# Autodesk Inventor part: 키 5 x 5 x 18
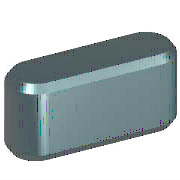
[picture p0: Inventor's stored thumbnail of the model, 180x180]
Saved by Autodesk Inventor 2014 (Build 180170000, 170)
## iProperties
Created: 2012-02
Part Number: 키 5 x 5 x 18
Material: 강철, 연강
Description: 키 및 해당 키홈
Document SubType Name: Modeling
Standard: KS B 1311
Designer: P15F
Standards Organization: KS
Language: ko-KR
Size Designation: 5 x 5 x 18
Categories: <MemberInstance><Categories><Category DisplayName="샤프트 부품" InternalName="7f7aeb1f-a693-4053-b835-cee3144e0d98" Mnemonic="SHFT"><Category DisplayName="키" Interna
Density: 1 g/cm^3
Appearance: Yellow
IsCustomPart: 1
Author: P15F
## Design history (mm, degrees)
sketch "스케치1"
  geometry: L1 (2.5, 2.5)-(15.5, 2.5); L2 (15.5, -2.5)-(2.5, -2.5); L3 (0, 9.4)-(0, -7.4) reference; L4 (-5, 0)-(30, 0) reference; L5 (18, 0)-(18, 7); A1 r 2.5 centre (2.5, 0) between (2.5, 2.5) and (2.5, -2.5); A2 r 2.5 centre (15.5, 0) between (15.5, -2.5) and (15.5, 2.5)
  constraints: 6 end point, 5 point on circle, 4 tangent, 3 point on line, 2 centre point, 1 horizontal, 1 parallel, 1 perpendicular
  dimensions: "d0" = 2.5 radius of A1 (= 0.5 x PB); "d13" = 2.5 radius of A2 (= 0.5 x PB); "d14" = 18 distance between parallel lines of L5 L3 (= NLG)
extrude "본체1" new body sketch "스케치1" taper "d3" = 0 deg; stored distance "d4" = 10
workplane "Work Plane3"
body "Solid1"
workplane "Work Plane1"
workplane "Work Plane2"
chamfer "모따기1" distance "d8" = 0.4 (= PHH); stored, may be unused: second distance "d9" = 0.4 (= PHH), angle "d15" = 45 deg
other parameters: "d1" = -3 (= -PNT), "d2" = 2 (= PH - PNT), "NLG" = 18 [user parameter; used in 3 equation terms], "PB" = 5 [user parameter; used in 2 equation terms], "PNT" = 3 [user parameter; used in 2 equation terms], "PH" = 5 [user parameter; used in 1 equation term], "PHH" = 0.4 [user parameter; used in 2 equation terms], "d10" = 0, "d16" = 0, "d17" = 0, "d18" = 0, "WDMIN" = 12 [user parameter], "PLB2" = 18 (= NLG) [user parameter], "WDMAX" = 17 [user parameter], "PLB1" = 18 (= NLG) [user parameter], "RR" = 0.16 [user parameter], "PUEB" = 2.3 [user parameter]
